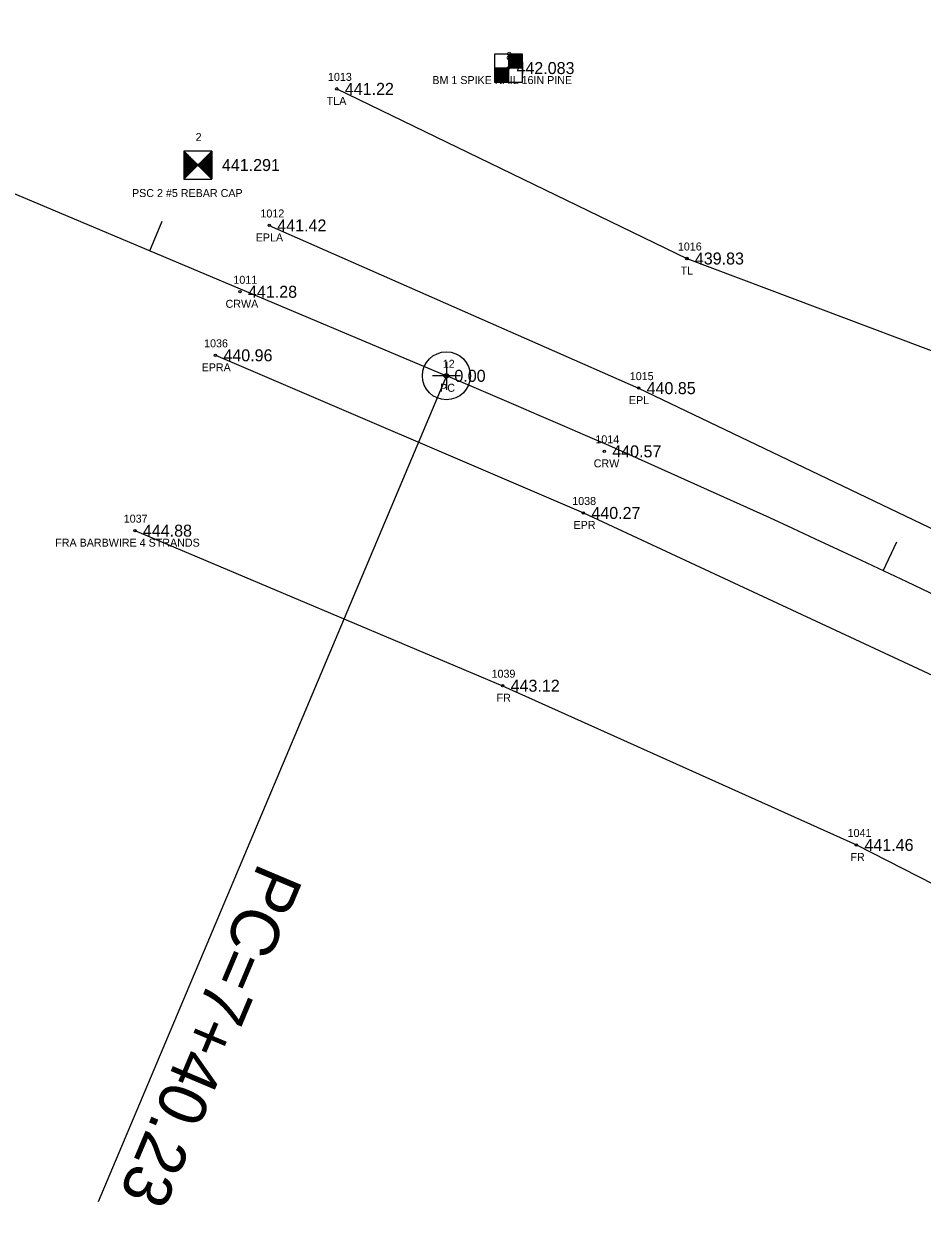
# Model space of a CAD drawing. Extents: x 1611865 to 1617004, y 775289 to 778546.
# Drawn here: x 1613838.2 to 1613950.5, y 777980.8 to 778129.4 of the extents above; entities that cross this region are included whole.
import ezdxf

# ---------------------------------------------------------------- set-up
doc = ezdxf.new("R2010")
doc.units = 0
for name, color, linetype in [('Default', 7, 'Continuous'), ('RD_EX_Fence_Other', 7, 'Continuous'), ('RD_EX_Fence_Other_txCode', 7, 'Continuous'), ('RD_EX_Road', 7, 'Continuous'), ('RD_EX_Road_txCode', 7, 'Continuous'), ('RD_EX_TX_Fence_Other_ELEV', 7, 'Continuous'), ('RD_EX_TX_Road_ELEV', 7, 'Continuous'), ('RD_EX_TX_VEG_ELEV', 7, 'Continuous'), ('RD_EX_VEG', 7, 'Continuous'), ('RD_EX_VEG_txCode', 7, 'Continuous'), ('RD_HC_Cl', 7, 'Continuous'), ('RD_HC_Data', 7, 'Continuous'), ('RD_HC_Data_Tic', 7, 'Continuous'), ('RD_HC_Survey', 7, 'Continuous'), ('RD_HC_Survey_ELEV', 7, 'Continuous'), ('RD_HC_Survey_txCode', 7, 'Continuous'), ('RD_HC_txCode', 7, 'Continuous'), ('RD_SMD_Locator', 7, 'Continuous')]:
    doc.layers.add(name, color=color, linetype=linetype)

msp = doc.modelspace()

# ---------------------------------------------------------------- linework, layer by layer
at = {"layer": 'Default'}
for p, q in [((1613254.24, 778353.78), (1613891, 778085.36)), ((1613891, 778087.11), (1613891, 778083.61)), ((1613892.75, 778085.36), (1613889.25, 778085.36))]:
    msp.add_line(p, q, dxfattribs=at)
msp.add_arc((1613334.62, 776765.46), 1432.38, 51.01411, 67.14296, dxfattribs=at)
msp.add_arc((1613334.62, 776765.46), 1432.38, 51.01411, 67.14296, dxfattribs=at)
at = {"layer": 'RD_EX_Fence_Other'}
msp.add_lwpolyline([(1613852.08, 778066.01), (1613898.03, 778046.63), (1613942.24, 778026.73), (1613986.54, 778004.12), (1614028.52, 777979.95), (1614066.85, 777959.39), (1614112.82, 777929.4), (1614150.64, 777902.78), (1614189.71, 777873.35), (1614229.91, 777841.27), (1614268.42, 777810.69), (1614347.33, 777746.8), (1614401.12, 777703.98), (1614396.2, 777691.06)], dxfattribs=at)
at = {"layer": 'RD_EX_Road'}
for points in [[(1613868.87, 778104.15), (1613915.02, 778083.82), (1613960.16, 778062.2), (1614004.58, 778040.28), (1614048.84, 778015.98), (1614091.38, 777990.08), (1614134.36, 777962.6), (1614174.73, 777933.48), (1614192.07, 777920.58), (1614215.93, 777904.23), (1614254.59, 777873.05), (1614293.82, 777842.42), (1614371.74, 777779.59), (1614449.33, 777716.3), (1614443.98, 777709.72), (1614439.38, 777704.09)], [(1613862.14, 778087.92), (1613908.12, 778068.22), (1613952.96, 778047.38), (1613997, 778025.09), (1614041.16, 778001.63), (1614124.35, 777949.06), (1614164.51, 777920.91), (1614187.11, 777904.29), (1614205.27, 777889.82), (1614244.49, 777859.52), (1614283.42, 777829.45), (1614361.06, 777765.89), (1614439.38, 777704.09)]]:
    msp.add_lwpolyline(points, dxfattribs=at)
at = {"layer": 'RD_EX_VEG'}
msp.add_lwpolyline([(1613877.31, 778121.22), (1613921.05, 778100.02), (1613970.15, 778081.54), (1614014.03, 778056.89), (1614062.61, 778034.99), (1614105.06, 778008.15), (1614147.57, 777982.51), (1614187.98, 777952.84), (1614226.4, 777922.61), (1614267.62, 777889.85), (1614307.16, 777859.76), (1614385.12, 777793.65), (1614491.14, 777728.5)], dxfattribs=at)
at = {"layer": 'RD_HC_Cl'}
msp.add_line((1613254.24, 778353.78), (1613891, 778085.36), dxfattribs=at)
msp.add_arc((1613334.62, 776765.46), 1432.38, 51.01411, 67.14296, dxfattribs=at)
at = {"layer": 'RD_HC_Data'}
msp.add_line((1613891, 778085.36), (1613847.48, 777982.12), dxfattribs=at)
for radius in [3, 0.282]:
    msp.add_circle((1613891, 778085.36), radius, dxfattribs=at)
at = {"layer": 'RD_HC_Data_Tic'}
for p, q in [((1613853.93, 778100.98), (1613855.49, 778104.67)), ((1613945.58, 778061), (1613947.29, 778064.62))]:
    msp.add_line(p, q, dxfattribs=at)
at = {"layer": 'RD_HC_Survey'}
for p, q in [((1613898.76, 778125.57), (1613898.76, 778122.07)), ((1613898.78, 778125.57), (1613898.78, 778123.82)), ((1613898.8, 778125.57), (1613898.8, 778123.82)), ((1613898.83, 778125.57), (1613898.83, 778123.82)), ((1613898.85, 778125.57), (1613898.85, 778123.82)), ((1613898.88, 778125.57), (1613898.88, 778123.82)), ((1613898.9, 778125.57), (1613898.9, 778123.82)), ((1613898.93, 778125.57), (1613898.93, 778123.82)), ((1613898.95, 778125.57), (1613898.95, 778123.82)), ((1613898.98, 778125.57), (1613898.98, 778123.82)), ((1613899, 778125.57), (1613899, 778123.82)), ((1613899.03, 778125.57), (1613899.03, 778123.82)), ((1613899.05, 778125.57), (1613899.05, 778123.82)), ((1613899.08, 778125.57), (1613899.08, 778123.82)), ((1613899.1, 778125.57), (1613899.1, 778123.82)), ((1613899.13, 778125.57), (1613899.13, 778123.82)), ((1613899.15, 778125.57), (1613899.15, 778123.82)), ((1613899.18, 778125.57), (1613899.18, 778123.82)), ((1613899.2, 778125.57), (1613899.2, 778123.82)), ((1613899.22, 778125.57), (1613899.22, 778123.82)), ((1613899.25, 778125.57), (1613899.25, 778123.82)), ((1613899.27, 778125.57), (1613899.27, 778123.82)), ((1613899.3, 778125.57), (1613899.3, 778123.82)), ((1613899.32, 778125.57), (1613899.32, 778123.82)), ((1613899.35, 778125.57), (1613899.35, 778123.82)), ((1613899.37, 778125.57), (1613899.37, 778123.82)), ((1613899.4, 778125.57), (1613899.4, 778123.82)), ((1613899.42, 778125.57), (1613899.42, 778123.82)), ((1613899.45, 778125.57), (1613899.45, 778123.82)), ((1613899.47, 778125.57), (1613899.47, 778123.82)), ((1613899.5, 778125.57), (1613899.5, 778123.82)), ((1613899.52, 778125.57), (1613899.52, 778123.82)), ((1613899.55, 778125.57), (1613899.55, 778123.82)), ((1613899.57, 778125.57), (1613899.57, 778123.82)), ((1613899.6, 778125.57), (1613899.6, 778123.82)), ((1613899.62, 778125.57), (1613899.62, 778123.82)), ((1613899.65, 778125.57), (1613899.65, 778123.82)), ((1613899.67, 778125.57), (1613899.67, 778123.82)), ((1613899.69, 778125.57), (1613899.69, 778123.82)), ((1613899.72, 778125.57), (1613899.72, 778123.82)), ((1613899.74, 778125.57), (1613899.74, 778123.82)), ((1613899.77, 778125.57), (1613899.77, 778123.82)), ((1613899.79, 778125.57), (1613899.79, 778123.82)), ((1613899.82, 778125.57), (1613899.82, 778123.82)), ((1613899.84, 778125.57), (1613899.84, 778123.82)), ((1613899.87, 778125.57), (1613899.87, 778123.82)), ((1613899.89, 778125.57), (1613899.89, 778123.82)), ((1613899.92, 778125.57), (1613899.92, 778123.82)), ((1613899.94, 778125.57), (1613899.94, 778123.82)), ((1613899.97, 778125.57), (1613899.97, 778123.82)), ((1613899.99, 778125.57), (1613899.99, 778123.82)), ((1613900.02, 778125.57), (1613900.02, 778123.82)), ((1613900.04, 778125.57), (1613900.04, 778123.82)), ((1613900.07, 778125.57), (1613900.07, 778123.82)), ((1613900.09, 778125.57), (1613900.09, 778123.82)), ((1613900.12, 778125.57), (1613900.12, 778123.82)), ((1613900.14, 778125.57), (1613900.14, 778123.82)), ((1613900.17, 778125.57), (1613900.17, 778123.82)), ((1613900.19, 778125.57), (1613900.19, 778123.82)), ((1613900.21, 778125.57), (1613900.21, 778123.82)), ((1613900.24, 778125.57), (1613900.24, 778123.82)), ((1613900.26, 778125.57), (1613900.26, 778123.82)), ((1613900.29, 778125.57), (1613900.29, 778123.82)), ((1613900.31, 778125.57), (1613900.31, 778123.82)), ((1613900.34, 778125.57), (1613900.34, 778123.82)), ((1613900.36, 778125.57), (1613900.36, 778123.82)), ((1613900.39, 778125.57), (1613900.39, 778123.82)), ((1613900.41, 778125.57), (1613900.41, 778123.82)), ((1613900.44, 778125.57), (1613900.44, 778123.82)), ((1613900.46, 778125.57), (1613900.46, 778123.82)), ((1613900.49, 778125.57), (1613900.49, 778123.82)), ((1613900.51, 778123.82), (1613897.01, 778123.82)), ((1613897.01, 778123.82), (1613897.01, 778122.07)), ((1613897.04, 778123.82), (1613897.04, 778122.07)), ((1613897.06, 778123.82), (1613897.06, 778122.07)), ((1613897.09, 778123.82), (1613897.09, 778122.07)), ((1613897.11, 778123.82), (1613897.11, 778122.07)), ((1613897.14, 778123.82), (1613897.14, 778122.07)), ((1613897.16, 778123.82), (1613897.16, 778122.07)), ((1613897.18, 778123.82), (1613897.18, 778122.07)), ((1613897.21, 778123.82), (1613897.21, 778122.07)), ((1613897.23, 778123.82), (1613897.23, 778122.07)), ((1613897.26, 778123.82), (1613897.26, 778122.07)), ((1613897.28, 778123.82), (1613897.28, 778122.07)), ((1613897.31, 778123.82), (1613897.31, 778122.07)), ((1613897.33, 778123.82), (1613897.33, 778122.07)), ((1613897.36, 778123.82), (1613897.36, 778122.07)), ((1613897.38, 778123.82), (1613897.38, 778122.07)), ((1613897.41, 778123.82), (1613897.41, 778122.07)), ((1613897.43, 778123.82), (1613897.43, 778122.07)), ((1613897.46, 778123.82), (1613897.46, 778122.07)), ((1613897.48, 778123.82), (1613897.48, 778122.07)), ((1613897.51, 778123.82), (1613897.51, 778122.07)), ((1613897.53, 778123.82), (1613897.53, 778122.07)), ((1613897.56, 778123.82), (1613897.56, 778122.07)), ((1613897.58, 778123.82), (1613897.58, 778122.07)), ((1613897.61, 778123.82), (1613897.61, 778122.07)), ((1613897.63, 778123.82), (1613897.63, 778122.07)), ((1613897.66, 778123.82), (1613897.66, 778122.07)), ((1613897.68, 778123.82), (1613897.68, 778122.07)), ((1613897.7, 778123.82), (1613897.7, 778122.07)), ((1613897.73, 778123.82), (1613897.73, 778122.07)), ((1613897.75, 778123.82), (1613897.75, 778122.07)), ((1613897.78, 778123.82), (1613897.78, 778122.07)), ((1613897.8, 778123.82), (1613897.8, 778122.07)), ((1613897.83, 778123.82), (1613897.83, 778122.07)), ((1613897.85, 778123.82), (1613897.85, 778122.07)), ((1613897.88, 778123.82), (1613897.88, 778122.07)), ((1613897.9, 778123.82), (1613897.9, 778122.07)), ((1613897.93, 778123.82), (1613897.93, 778122.07)), ((1613897.95, 778123.82), (1613897.95, 778122.07)), ((1613897.98, 778123.82), (1613897.98, 778122.07)), ((1613898, 778123.82), (1613898, 778122.07)), ((1613898.03, 778123.82), (1613898.03, 778122.07)), ((1613898.05, 778123.82), (1613898.05, 778122.07)), ((1613898.08, 778123.82), (1613898.08, 778122.07)), ((1613898.1, 778123.82), (1613898.1, 778122.07)), ((1613898.13, 778123.82), (1613898.13, 778122.07)), ((1613898.15, 778123.82), (1613898.15, 778122.07)), ((1613898.17, 778123.82), (1613898.17, 778122.07)), ((1613898.2, 778123.82), (1613898.2, 778122.07)), ((1613898.22, 778123.82), (1613898.22, 778122.07)), ((1613898.25, 778123.82), (1613898.25, 778122.07)), ((1613898.27, 778123.82), (1613898.27, 778122.07)), ((1613898.3, 778123.82), (1613898.3, 778122.07)), ((1613898.32, 778123.82), (1613898.32, 778122.07)), ((1613898.35, 778123.82), (1613898.35, 778122.07)), ((1613898.37, 778123.82), (1613898.37, 778122.07)), ((1613898.4, 778123.82), (1613898.4, 778122.07)), ((1613898.42, 778123.82), (1613898.42, 778122.07)), ((1613898.45, 778123.82), (1613898.45, 778122.07)), ((1613898.47, 778123.82), (1613898.47, 778122.07)), ((1613898.5, 778123.82), (1613898.5, 778122.07)), ((1613898.52, 778123.82), (1613898.52, 778122.07)), ((1613898.55, 778123.82), (1613898.55, 778122.07)), ((1613898.57, 778123.82), (1613898.57, 778122.07)), ((1613898.6, 778123.82), (1613898.6, 778122.07)), ((1613898.62, 778123.82), (1613898.62, 778122.07)), ((1613898.65, 778123.82), (1613898.65, 778122.07)), ((1613898.67, 778123.82), (1613898.67, 778122.07)), ((1613898.69, 778123.82), (1613898.69, 778122.07)), ((1613898.72, 778123.82), (1613898.72, 778122.07)), ((1613898.74, 778123.82), (1613898.74, 778122.07)), ((1613858.2, 778113.45), (1613861.7, 778109.95)), ((1613861.7, 778113.45), (1613858.2, 778109.95)), ((1613858.22, 778113.43), (1613858.22, 778109.97)), ((1613858.25, 778113.4), (1613858.25, 778110)), ((1613858.27, 778113.38), (1613858.27, 778110.02)), ((1613858.3, 778113.35), (1613858.3, 778110.05)), ((1613858.32, 778113.33), (1613858.32, 778110.07)), ((1613858.35, 778113.3), (1613858.35, 778110.1)), ((1613858.37, 778113.28), (1613858.37, 778110.12)), ((1613858.4, 778113.25), (1613858.4, 778110.15)), ((1613858.42, 778113.23), (1613858.42, 778110.17)), ((1613858.45, 778113.2), (1613858.45, 778110.2)), ((1613858.47, 778113.18), (1613858.47, 778110.22)), ((1613858.5, 778113.15), (1613858.5, 778110.25)), ((1613858.52, 778113.13), (1613858.52, 778110.27)), ((1613858.55, 778113.1), (1613858.55, 778110.3)), ((1613858.57, 778113.08), (1613858.57, 778110.32)), ((1613858.6, 778113.05), (1613858.6, 778110.35)), ((1613858.62, 778113.03), (1613858.62, 778110.37)), ((1613858.65, 778113), (1613858.65, 778110.4)), ((1613858.67, 778112.98), (1613858.67, 778110.42)), ((1613858.69, 778112.96), (1613858.69, 778110.44)), ((1613858.72, 778112.93), (1613858.72, 778110.47)), ((1613858.74, 778112.91), (1613858.74, 778110.49)), ((1613858.77, 778112.88), (1613858.77, 778110.52)), ((1613858.79, 778112.86), (1613858.79, 778110.54)), ((1613858.82, 778112.83), (1613858.82, 778110.57)), ((1613858.84, 778112.81), (1613858.84, 778110.59)), ((1613858.87, 778112.78), (1613858.87, 778110.62)), ((1613858.89, 778112.76), (1613858.89, 778110.64)), ((1613858.92, 778112.73), (1613858.92, 778110.67)), ((1613860.98, 778112.73), (1613860.98, 778110.67)), ((1613861.01, 778112.76), (1613861.01, 778110.64)), ((1613861.03, 778112.78), (1613861.03, 778110.62)), ((1613861.06, 778112.81), (1613861.06, 778110.59)), ((1613861.08, 778112.83), (1613861.08, 778110.57)), ((1613861.11, 778112.86), (1613861.11, 778110.54)), ((1613861.13, 778112.88), (1613861.13, 778110.52)), ((1613861.16, 778112.91), (1613861.16, 778110.49)), ((1613861.18, 778112.93), (1613861.18, 778110.47)), ((1613861.21, 778112.96), (1613861.21, 778110.44)), ((1613861.23, 778112.98), (1613861.23, 778110.42)), ((1613861.25, 778113), (1613861.25, 778110.4)), ((1613861.28, 778113.03), (1613861.28, 778110.37)), ((1613861.3, 778113.05), (1613861.3, 778110.35)), ((1613861.33, 778113.08), (1613861.33, 778110.32)), ((1613861.35, 778113.1), (1613861.35, 778110.3)), ((1613861.38, 778113.13), (1613861.38, 778110.27)), ((1613861.4, 778113.15), (1613861.4, 778110.25)), ((1613861.43, 778113.18), (1613861.43, 778110.22)), ((1613861.45, 778113.2), (1613861.45, 778110.2)), ((1613861.48, 778113.23), (1613861.48, 778110.17)), ((1613861.5, 778113.25), (1613861.5, 778110.15)), ((1613861.53, 778113.28), (1613861.53, 778110.12)), ((1613861.55, 778113.3), (1613861.55, 778110.1)), ((1613861.58, 778113.33), (1613861.58, 778110.07)), ((1613861.6, 778113.35), (1613861.6, 778110.05)), ((1613861.63, 778113.38), (1613861.63, 778110.02)), ((1613861.65, 778113.4), (1613861.65, 778110)), ((1613861.68, 778113.43), (1613861.68, 778109.97)), ((1613858.94, 778112.71), (1613858.94, 778110.69)), ((1613858.97, 778112.68), (1613858.97, 778110.72)), ((1613858.99, 778112.66), (1613858.99, 778110.74)), ((1613859.02, 778112.63), (1613859.02, 778110.77)), ((1613859.04, 778112.61), (1613859.04, 778110.79)), ((1613859.07, 778112.58), (1613859.07, 778110.82)), ((1613859.09, 778112.56), (1613859.09, 778110.84)), ((1613859.12, 778112.53), (1613859.12, 778110.87)), ((1613859.14, 778112.51), (1613859.14, 778110.89)), ((1613859.17, 778112.48), (1613859.17, 778110.92)), ((1613859.19, 778112.46), (1613859.19, 778110.94)), ((1613859.21, 778112.44), (1613859.21, 778110.96)), ((1613859.24, 778112.41), (1613859.24, 778110.99)), ((1613859.26, 778112.39), (1613859.26, 778111.01)), ((1613859.29, 778112.36), (1613859.29, 778111.04)), ((1613859.31, 778112.34), (1613859.31, 778111.06)), ((1613859.34, 778112.31), (1613859.34, 778111.09)), ((1613859.36, 778112.29), (1613859.36, 778111.11)), ((1613859.39, 778112.26), (1613859.39, 778111.14)), ((1613859.41, 778112.24), (1613859.41, 778111.16)), ((1613859.44, 778112.21), (1613859.44, 778111.19)), ((1613859.46, 778112.19), (1613859.46, 778111.21)), ((1613859.49, 778112.16), (1613859.49, 778111.24)), ((1613859.51, 778112.14), (1613859.51, 778111.26)), ((1613859.54, 778112.11), (1613859.54, 778111.29)), ((1613859.56, 778112.09), (1613859.56, 778111.31)), ((1613859.59, 778112.06), (1613859.59, 778111.34)), ((1613859.61, 778112.04), (1613859.61, 778111.36)), ((1613859.64, 778112.01), (1613859.64, 778111.39)), ((1613859.66, 778111.99), (1613859.66, 778111.41)), ((1613859.68, 778111.97), (1613859.68, 778111.43)), ((1613859.71, 778111.94), (1613859.71, 778111.46)), ((1613859.73, 778111.92), (1613859.73, 778111.48)), ((1613859.76, 778111.89), (1613859.76, 778111.51)), ((1613859.78, 778111.87), (1613859.78, 778111.53)), ((1613859.81, 778111.84), (1613859.81, 778111.56)), ((1613859.83, 778111.82), (1613859.83, 778111.58)), ((1613859.86, 778111.79), (1613859.86, 778111.61)), ((1613859.88, 778111.77), (1613859.88, 778111.63)), ((1613859.91, 778111.74), (1613859.91, 778111.66)), ((1613859.93, 778111.72), (1613859.93, 778111.68)), ((1613859.97, 778111.72), (1613859.97, 778111.68)), ((1613859.99, 778111.74), (1613859.99, 778111.66)), ((1613860.02, 778111.77), (1613860.02, 778111.63)), ((1613860.04, 778111.79), (1613860.04, 778111.61)), ((1613860.07, 778111.82), (1613860.07, 778111.58)), ((1613860.09, 778111.84), (1613860.09, 778111.56)), ((1613860.12, 778111.87), (1613860.12, 778111.53)), ((1613860.14, 778111.89), (1613860.14, 778111.51)), ((1613860.17, 778111.92), (1613860.17, 778111.48)), ((1613860.19, 778111.94), (1613860.19, 778111.46)), ((1613860.22, 778111.97), (1613860.22, 778111.43)), ((1613860.24, 778111.99), (1613860.24, 778111.41)), ((1613860.26, 778112.01), (1613860.26, 778111.39)), ((1613860.29, 778112.04), (1613860.29, 778111.36)), ((1613860.31, 778112.06), (1613860.31, 778111.34)), ((1613860.34, 778112.09), (1613860.34, 778111.31)), ((1613860.36, 778112.11), (1613860.36, 778111.29)), ((1613860.39, 778112.14), (1613860.39, 778111.26)), ((1613860.41, 778112.16), (1613860.41, 778111.24)), ((1613860.44, 778112.19), (1613860.44, 778111.21)), ((1613860.46, 778112.21), (1613860.46, 778111.19)), ((1613860.49, 778112.24), (1613860.49, 778111.16)), ((1613860.51, 778112.26), (1613860.51, 778111.14)), ((1613860.54, 778112.29), (1613860.54, 778111.11)), ((1613860.56, 778112.31), (1613860.56, 778111.09)), ((1613860.59, 778112.34), (1613860.59, 778111.06)), ((1613860.61, 778112.36), (1613860.61, 778111.04)), ((1613860.64, 778112.39), (1613860.64, 778111.01)), ((1613860.66, 778112.41), (1613860.66, 778110.99)), ((1613860.69, 778112.44), (1613860.69, 778110.96)), ((1613860.71, 778112.46), (1613860.71, 778110.94)), ((1613860.73, 778112.48), (1613860.73, 778110.92)), ((1613860.76, 778112.51), (1613860.76, 778110.89)), ((1613860.78, 778112.53), (1613860.78, 778110.87)), ((1613860.81, 778112.56), (1613860.81, 778110.84)), ((1613860.83, 778112.58), (1613860.83, 778110.82)), ((1613860.86, 778112.61), (1613860.86, 778110.79)), ((1613860.88, 778112.63), (1613860.88, 778110.77)), ((1613860.91, 778112.66), (1613860.91, 778110.74)), ((1613860.93, 778112.68), (1613860.93, 778110.72)), ((1613860.96, 778112.71), (1613860.96, 778110.69))]:
    msp.add_line(p, q, dxfattribs=at)
for points in [[(1613900.51, 778125.57), (1613897.01, 778125.57), (1613897.01, 778122.07), (1613900.51, 778122.07)], [(1613861.7, 778113.45), (1613858.2, 778113.45), (1613858.2, 778109.95), (1613861.7, 778109.95)]]:
    msp.add_lwpolyline(points, close=True, dxfattribs=at)
at = {"layer": 'RD_SMD_Locator'}
for centre in [(1613898.76, 778123.82), (1613877.31, 778121.22), (1613859.95, 778111.7), (1613868.87, 778104.15), (1613921.05, 778100.02), (1613865.21, 778095.86), (1613862.14, 778087.92), (1613891, 778085.36), (1613915.02, 778083.82), (1613910.73, 778075.92), (1613908.12, 778068.22), (1613852.08, 778066.01), (1613898.03, 778046.63), (1613942.24, 778026.73)]:
    msp.add_circle(centre, 0.15, dxfattribs=at)

# ---------------------------------------------------------------- texts
at = {"layer": 'RD_EX_Fence_Other_txCode'}
for s, p in [('1037', (1613850.69, 778067.01)), ('FRA BARBWIRE 4 STRANDS', (1613842.13, 778064.01)), ('1039', (1613896.65, 778047.63)), ('FR', (1613897.28, 778044.63)), ('1041', (1613941.14, 778027.73)), ('FR', (1613941.49, 778024.73))]:
    msp.add_text(s, height=1, dxfattribs=at).set_placement(p)
at = {"layer": 'RD_EX_Road_txCode'}
for s, p in [('1012', (1613867.77, 778105.15)), ('EPLA', (1613867.18, 778102.15)), ('1036', (1613860.73, 778088.92)), ('EPRA', (1613860.42, 778085.92)), ('1015', (1613913.92, 778084.82)), ('EPL', (1613913.81, 778081.82)), ('1038', (1613906.73, 778069.22)), ('EPR', (1613906.89, 778066.22))]:
    msp.add_text(s, height=1, dxfattribs=at).set_placement(p)
at = {"layer": 'RD_EX_TX_Fence_Other_ELEV'}
for s, p in [('444.88', (1613853.08, 778065.26)), ('443.12', (1613899.03, 778045.88)), ('441.46', (1613943.24, 778025.98))]:
    msp.add_text(s, height=1.5, dxfattribs=at).set_placement(p)
at = {"layer": 'RD_EX_TX_Road_ELEV'}
for s, p in [('441.42', (1613869.87, 778103.4)), ('440.96', (1613863.14, 778087.17)), ('440.85', (1613916.02, 778083.07)), ('440.27', (1613909.12, 778067.47))]:
    msp.add_text(s, height=1.5, dxfattribs=at).set_placement(p)
at = {"layer": 'RD_EX_TX_VEG_ELEV'}
for s, p in [('441.22', (1613878.31, 778120.47)), ('439.83', (1613922.05, 778099.27))]:
    msp.add_text(s, height=1.5, dxfattribs=at).set_placement(p)
at = {"layer": 'RD_EX_VEG_txCode'}
for s, p in [('1013', (1613876.21, 778122.22)), ('TLA', (1613876.05, 778119.22)), ('1016', (1613919.93, 778101.02)), ('TL', (1613920.28, 778098.02))]:
    msp.add_text(s, height=1, dxfattribs=at).set_placement(p)
at = {"layer": 'RD_HC_Data'}
msp.add_text('PC=7+40.23', height=6, rotation=247.143, dxfattribs=at).set_placement((1613867.6, 778024.68))
at = {"layer": 'RD_HC_Survey_ELEV'}
for s, p in [('442.083', (1613899.76, 778123.07)), ('441.291', (1613862.95, 778110.95)), ('441.28', (1613866.21, 778095.11)), ('0.00', (1613892, 778084.61)), ('440.57', (1613911.73, 778075.17))]:
    msp.add_text(s, height=1.5, dxfattribs=at).set_placement(p)
at = {"layer": 'RD_HC_Survey_txCode'}
for s, p in [('8', (1613898.48, 778124.82)), ('BM 1 SPIKE NAIL 16IN PINE', (1613889.25, 778121.82)), ('1011', (1613864.39, 778096.86)), ('CRWA', (1613863.41, 778093.86)), ('1014', (1613909.62, 778076.92)), ('CRW', (1613909.41, 778073.92))]:
    msp.add_text(s, height=1, dxfattribs=at).set_placement(p)
at = {"layer": 'RD_HC_txCode'}
for s, p in [('2', (1613859.67, 778114.7)), ('PSC 2 #5 REBAR CAP', (1613851.72, 778107.7)), ('12', (1613890.55, 778086.36)), ('PC', (1613890.22, 778083.36))]:
    msp.add_text(s, height=1, dxfattribs=at).set_placement(p)

doc.saveas('drawing.dxf')
